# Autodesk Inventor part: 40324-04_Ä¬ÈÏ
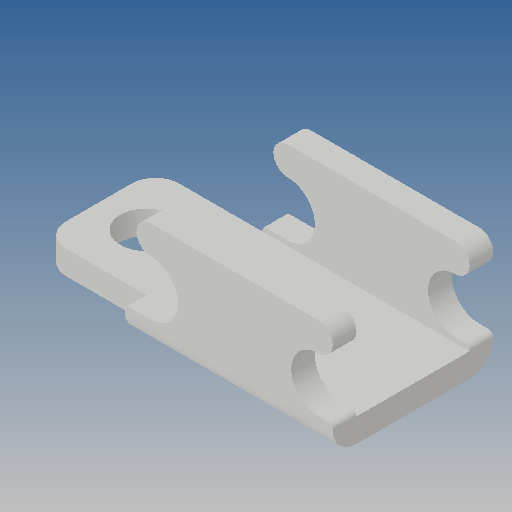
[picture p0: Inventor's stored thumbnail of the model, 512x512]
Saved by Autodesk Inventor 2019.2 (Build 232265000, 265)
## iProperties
Created: 2010-06
Part Number: 40324-04_Ä¬ÈÏ
Material: Ogólny
Document SubType Name: Modeling
Designer: CADENGINEERING4
Density: 1 g/cm^3
Appearance: Domyślna
Author: CADENGINEERING4
Revision Number: ÈÎºÎ
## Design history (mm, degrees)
feature "NONE"
node "Bryła1"
